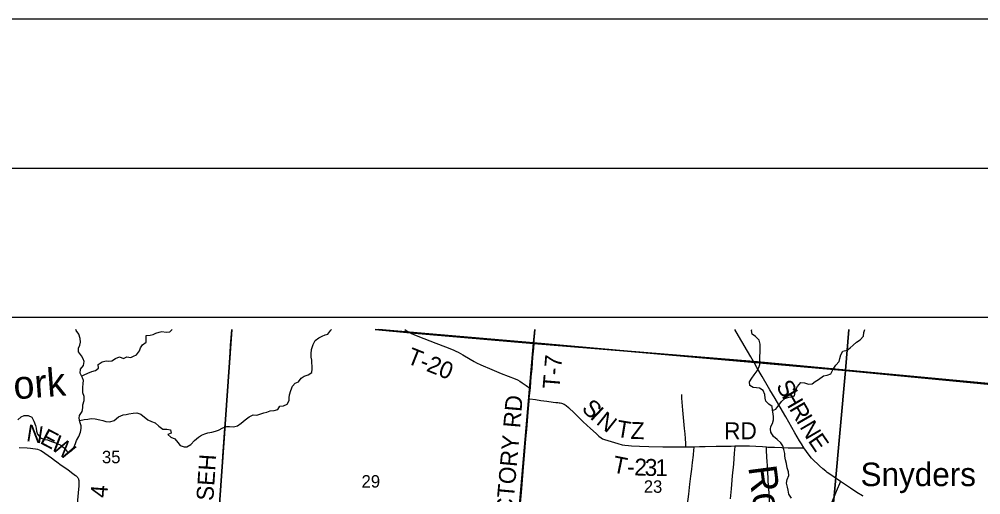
# Model space of a CAD drawing. Extents: x 0 to 34, y 0 to 22.
# Drawn here: x 3.306 to 6.536, y 20.403 to 22 of the extents above; entities that cross this region are included whole.
import ezdxf

# ---------------------------------------------------------------- set-up
doc = ezdxf.new("R2010")
doc.units = 0
for name, color, linetype in [('GM_X_Corporation', 7, 'Continuous'), ('GM_X_County_Road', 7, 'Continuous'), ('GM_X_County_Road_Text', 7, 'Continuous'), ('GM_X_Minor_River', 7, 'Continuous'), ('GM_X_Minor_River_Text', 7, 'Continuous'), ('GM_X_Section_Text', 7, 'Continuous'), ('GM_X_Township_Road', 7, 'Continuous'), ('GM_X_Township_Road_Text', 7, 'Continuous'), ('GM_X_Unincorporated_Text', 7, 'Continuous'), ('SH_Border', 7, 'Continuous'), ('SH_Cut_Line', 7, 'Continuous'), ('SH_Data', 7, 'Continuous')]:
    doc.layers.add(name, color=color, linetype=linetype)

msp = doc.modelspace()

# ---------------------------------------------------------------- linework, layer by layer
at = {"layer": 'GM_X_Corporation'}
for points in [[(4.0205, 20.9578), (3.9531, 20.0055), (2.9941, 20.0934), (3.0731, 20.9578)], [(4.5135, 20.9578), (5.0343, 20.9135), (4.9476, 19.9136), (3.9531, 20.0055), (4.0205, 20.9578)], [(4.9888, 20.3752), (4.9933, 20.4247), (4.9996, 20.4957), (5.004, 20.5483), (5.0073, 20.5914), (5.01, 20.6222), (5.015, 20.681), (5.018, 20.7181), (5.0187, 20.7263), (5.0223, 20.7637), (5.0238, 20.781), (5.0254, 20.7991), (5.0279, 20.8272), (5.031, 20.8652), (5.0337, 20.8956), (5.035, 20.9107), (4.6203, 20.9474), (4.5018, 20.9578)], [(4.5018, 20.9578), (4.6203, 20.9474), (5.035, 20.9107), (5.7735, 20.8502), (6.6577, 20.768)], [(5.0385, 20.9578), (5.0343, 20.9135), (4.5135, 20.9578)], [(6.0929, 20.9578), (6.0823, 20.8206), (5.0343, 20.9135), (5.0385, 20.9578)], [(7.1025, 20.9578), (7.0822, 20.7243), (6.0823, 20.8206), (6.0929, 20.9578)], [(6.6577, 20.768), (5.7735, 20.8502), (5.035, 20.9107), (5.0337, 20.8956), (5.031, 20.8652), (5.0279, 20.8272), (5.0254, 20.7991), (5.0238, 20.781), (5.0223, 20.7637), (5.0187, 20.7263), (5.018, 20.7181), (5.015, 20.681), (5.01, 20.6222), (5.0073, 20.5914), (5.004, 20.5483), (4.9996, 20.4957), (4.9933, 20.4247), (4.9888, 20.3752)]]:
    msp.add_lwpolyline(points, dxfattribs=at)
for points in [[(5.0343, 20.9135), (6.0823, 20.8206), (5.9917, 19.818), (4.9476, 19.9136)], [(6.0823, 20.8206), (7.0822, 20.7243), (6.9896, 19.7221), (5.9917, 19.818)]]:
    msp.add_lwpolyline(points, close=True, dxfattribs=at)
at = {"layer": 'GM_X_County_Road'}
for points in [[(5.7732, 20.8505), (5.7641, 20.8663), (5.7228, 20.9373), (5.7106, 20.9578)], [(5.9421, 20.561), (5.934, 20.574), (5.9278, 20.5847), (5.9122, 20.6116), (5.8812, 20.6652), (5.8703, 20.684), (5.8451, 20.7269), (5.8278, 20.7559), (5.8233, 20.7638), (5.8018, 20.8005), (5.7845, 20.8309), (5.7737, 20.8497), (5.7732, 20.8505)], [(3.3064, 20.5623), (3.3328, 20.5606), (3.3439, 20.5597), (3.3521, 20.5587), (3.3613, 20.5573), (3.3674, 20.5559), (3.3734, 20.5539), (3.3792, 20.5514), (3.3847, 20.5484), (3.3925, 20.5432), (3.4151, 20.5269), (3.4251, 20.5196), (3.4327, 20.5142), (3.4477, 20.5031), (3.4595, 20.4946), (3.4704, 20.4866), (3.4861, 20.4752), (3.4952, 20.4685), (3.4978, 20.4665), (3.5006, 20.4638), (3.5022, 20.4615), (3.5039, 20.4592), (3.5051, 20.4567), (3.5061, 20.454), (3.5067, 20.4509), (3.507, 20.4473), (3.5071, 20.4434), (3.5067, 20.4379), (3.5063, 20.4323), (3.5055, 20.4224), (3.4989, 20.3481)], [(6.0653, 20.4481), (6.0435, 20.4626), (6.026, 20.475), (6.0208, 20.4785), (6.0159, 20.4824), (6.0062, 20.4902), (5.9945, 20.5003), (5.9877, 20.5066), (5.9766, 20.5172), (5.9682, 20.5263), (5.9603, 20.5359), (5.951, 20.5482), (5.9421, 20.561)], [(6.1407, 20.3981), (6.1389, 20.3992), (6.1205, 20.4114), (6.0992, 20.4255), (6.0683, 20.4461), (6.0653, 20.4481)]]:
    msp.add_lwpolyline(points, dxfattribs=at)
at = {"layer": 'GM_X_Minor_River'}
for points in [[(3.3021, 20.6548), (3.3132, 20.665), (3.3231, 20.669), (3.3364, 20.6692), (3.3485, 20.6638), (3.356, 20.6504), (3.3615, 20.6359), (3.3629, 20.6264), (3.365, 20.6165), (3.3683, 20.6069), (3.3784, 20.5943), (3.3913, 20.5884), (3.4015, 20.5875), (3.4147, 20.582), (3.4246, 20.5785), (3.4344, 20.5753), (3.4465, 20.5699), (3.4589, 20.5595), (3.469, 20.5468), (3.4816, 20.5505), (3.4901, 20.5618), (3.4956, 20.5754), (3.4991, 20.5852), (3.5072, 20.5992), (3.5128, 20.6139), (3.5148, 20.6253), (3.5149, 20.6352), (3.5105, 20.6482), (3.508, 20.6604), (3.5089, 20.6699), (3.5174, 20.6831), (3.5202, 20.6956), (3.5204, 20.7054), (3.5247, 20.7198), (3.5245, 20.7331), (3.5197, 20.7461), (3.52, 20.7636), (3.5213, 20.7769), (3.5221, 20.7864), (3.5188, 20.7963), (3.5111, 20.8112), (3.5124, 20.8249), (3.5224, 20.8373), (3.5249, 20.8506), (3.5216, 20.8601), (3.516, 20.8697), (3.5059, 20.8827), (3.506, 20.8956), (3.5096, 20.9055), (3.5128, 20.9153), (3.5114, 20.9279), (3.5062, 20.942), (3.4981, 20.9546), (3.4963, 20.9578)], [(3.5095, 20.6531), (3.5247, 20.6556), (3.5372, 20.6574), (3.5486, 20.6591), (3.5616, 20.6586), (3.5767, 20.6546), (3.5873, 20.6522), (3.5979, 20.6494), (3.6108, 20.6481), (3.6249, 20.6521), (3.6399, 20.6653), (3.6552, 20.6712), (3.6654, 20.6729), (3.675, 20.6751), (3.6887, 20.6776), (3.7012, 20.6782), (3.7145, 20.6742), (3.7389, 20.655), (3.751, 20.6491), (3.7631, 20.6452), (3.7755, 20.6336), (3.7883, 20.6236), (3.8019, 20.6234), (3.8141, 20.621), (3.8173, 20.6096), (3.8051, 20.6055), (3.8157, 20.5967), (3.8289, 20.5908), (3.8394, 20.5789), (3.8472, 20.5689), (3.8601, 20.5638), (3.8699, 20.5637), (3.8833, 20.5715), (3.8957, 20.5858), (3.9087, 20.5967), (3.9191, 20.603), (3.9298, 20.6078), (3.9397, 20.6115), (3.953, 20.6136), (3.966, 20.6165), (3.9763, 20.6202), (3.9908, 20.6284), (4.0034, 20.6321), (4.0129, 20.6323), (4.0262, 20.6318), (4.0399, 20.635), (4.0518, 20.6433), (4.0652, 20.6545), (4.079, 20.6654), (4.092, 20.6717), (4.1045, 20.6708), (4.1179, 20.6748), (4.1286, 20.6789), (4.1385, 20.681), (4.1495, 20.6847), (4.1628, 20.6861), (4.175, 20.6893), (4.1813, 20.7007), (4.1938, 20.7024), (4.2068, 20.7072), (4.213, 20.7193), (4.2128, 20.7292), (4.214, 20.739), (4.2184, 20.7534), (4.2239, 20.7674), (4.2335, 20.778), (4.245, 20.7824), (4.2535, 20.7948), (4.2634, 20.8019), (4.2772, 20.8063), (4.2894, 20.8142), (4.2907, 20.8263), (4.2901, 20.8358), (4.2898, 20.8453), (4.2888, 20.8552), (4.287, 20.8648), (4.2868, 20.8765), (4.2881, 20.891), (4.2936, 20.908), (4.3007, 20.9208), (4.3133, 20.9302), (4.3244, 20.9358), (4.3339, 20.9398), (4.3435, 20.9424), (4.3535, 20.9563), (4.3555, 20.9578)], [(3.516, 20.8018), (3.5247, 20.8057), (3.5369, 20.812), (3.5499, 20.8168), (3.5628, 20.8201), (3.5724, 20.8283), (3.5711, 20.8405), (3.5852, 20.8498), (3.5982, 20.8527), (3.6077, 20.8522), (3.6176, 20.8529), (3.6302, 20.8611), (3.6432, 20.8663), (3.6568, 20.8604), (3.6675, 20.8664), (3.6808, 20.8643), (3.6903, 20.8687), (3.7003, 20.8736), (3.7099, 20.8871), (3.7142, 20.897), (3.7204, 20.9072), (3.7323, 20.9161), (3.7332, 20.9264), (3.7326, 20.9386), (3.7463, 20.9388), (3.7558, 20.9409), (3.7657, 20.9461), (3.7764, 20.9487), (3.7859, 20.9512), (3.8, 20.9488), (3.8129, 20.9501), (3.8205, 20.9578)], [(5.9004, 20.3923), (5.891, 20.4053), (5.8893, 20.4182), (5.8875, 20.4285), (5.8835, 20.4419), (5.886, 20.4548), (5.8911, 20.468), (5.8908, 20.4798), (5.8864, 20.4932), (5.8836, 20.508), (5.8807, 20.521), (5.8786, 20.5324), (5.8776, 20.542), (5.8751, 20.5549), (5.8714, 20.5675), (5.8647, 20.5771), (5.8523, 20.5894), (5.8403, 20.5994), (5.831, 20.6132), (5.8304, 20.6231), (5.8316, 20.6326), (5.8371, 20.6424), (5.8406, 20.6549), (5.8396, 20.6648), (5.839, 20.6747), (5.8365, 20.6869), (5.8359, 20.6991), (5.8246, 20.7072), (5.8145, 20.7176), (5.8123, 20.7275), (5.8113, 20.7404), (5.805, 20.7534), (5.793, 20.7616), (5.7835, 20.7624), (5.7717, 20.7633), (5.7604, 20.7699), (5.7598, 20.7821), (5.7676, 20.7953), (5.7749, 20.8063), (5.785, 20.8195), (5.7912, 20.8308), (5.7936, 20.841), (5.7947, 20.8684), (5.7953, 20.8805), (5.795, 20.89), (5.7955, 20.8999), (5.7956, 20.9094), (5.792, 20.9224), (5.7796, 20.9347), (5.7679, 20.9421), (5.7662, 20.9546), (5.7675, 20.9578)], [(5.9914, 20.7905), (6.0081, 20.8023), (6.0206, 20.8048), (6.0327, 20.8093), (6.0404, 20.8252), (6.0496, 20.8384), (6.061, 20.8505), (6.0634, 20.8607), (6.0661, 20.8736), (6.0734, 20.8857), (6.0871, 20.889), (6.0977, 20.8965), (6.1076, 20.9056), (6.1183, 20.9154), (6.1316, 20.9236), (6.1419, 20.9357), (6.1439, 20.9486), (6.1468, 20.9578)], [(5.8366, 20.6862), (5.8476, 20.6906), (5.8576, 20.7038), (5.8665, 20.7162), (5.878, 20.7267), (5.891, 20.7311), (5.9013, 20.7326), (5.9108, 20.7359), (5.9141, 20.7545), (5.9207, 20.7665), (5.9323, 20.7805), (5.944, 20.7796), (5.958, 20.7741), (5.9698, 20.7755), (5.9805, 20.7837), (5.9914, 20.7905)]]:
    msp.add_lwpolyline(points, dxfattribs=at)
at = {"layer": 'GM_X_Township_Road'}
for p, q in [((5.0352, 20.9101), (5.0395, 20.9578)), ((5.019, 20.7257), (5.0225, 20.7631))]:
    msp.add_line(p, q, dxfattribs=at)
for points in [[(3.9812, 20.3914), (3.9833, 20.4223), (3.9843, 20.4378), (3.9854, 20.4564), (3.9879, 20.4937), (3.9907, 20.534), (3.9941, 20.5805), (3.9986, 20.6425), (4.0002, 20.6642), (4.0027, 20.7014), (4.0058, 20.7448), (4.008, 20.7789), (4.0101, 20.8099), (4.0126, 20.8471), (4.0149, 20.8813), (4.0166, 20.9061), (4.0193, 20.9433), (4.0205, 20.9578)], [(4.6019, 20.9578), (4.6057, 20.9553), (4.6121, 20.9512), (4.6159, 20.9491), (4.6206, 20.9468)], [(4.6206, 20.9468), (4.6244, 20.945), (4.6315, 20.9419), (4.6455, 20.936), (4.7061, 20.9118), (4.7379, 20.8995), (4.764, 20.8895), (4.7725, 20.8858), (4.7808, 20.8817), (4.797, 20.8726), (4.8209, 20.8581), (4.8343, 20.8502), (4.8425, 20.8458), (4.8567, 20.8393), (4.894, 20.8238), (4.9256, 20.8107), (4.9487, 20.8017), (4.9718, 20.7925), (4.9802, 20.7887), (4.9884, 20.7844), (4.9962, 20.7794), (5.0088, 20.7704), (5.0141, 20.767), (5.0173, 20.7651), (5.0192, 20.7642), (5.0209, 20.7636), (5.0225, 20.7631)], [(5.0225, 20.7631), (5.0241, 20.7805), (5.0256, 20.7986), (5.0281, 20.8267), (5.0313, 20.8647), (5.0339, 20.895), (5.0352, 20.9101)], [(5.5459, 20.5641), (5.5458, 20.5666), (5.5454, 20.5749), (5.5445, 20.5917), (5.5429, 20.6074), (5.5409, 20.6253), (5.538, 20.6631), (5.5359, 20.6879), (5.5327, 20.7277), (5.5319, 20.7404)], [(4.9727, 20.1756), (4.9726, 20.1767), (4.9728, 20.186), (4.9738, 20.1984), (4.9776, 20.2417), (4.9852, 20.3314), (4.989, 20.3747), (4.9935, 20.4241), (4.9998, 20.4952), (5.0042, 20.5478), (5.0075, 20.5909), (5.0103, 20.6217), (5.0152, 20.6805), (5.0182, 20.7176), (5.019, 20.7257)], [(5.019, 20.7257), (5.0213, 20.7254), (5.0411, 20.7226), (5.0583, 20.7199), (5.0785, 20.7173), (5.1004, 20.7145), (5.1094, 20.7134), (5.116, 20.7126), (5.12, 20.7122), (5.1239, 20.7115), (5.1275, 20.7107), (5.1309, 20.7098), (5.1341, 20.7087), (5.1371, 20.7072), (5.1399, 20.7055), (5.1432, 20.7034), (5.1519, 20.6959), (5.1719, 20.6769), (5.2008, 20.6487), (5.2256, 20.6253), (5.2439, 20.6085), (5.2534, 20.6004), (5.2609, 20.5947), (5.2662, 20.5914), (5.272, 20.5888), (5.2839, 20.585), (5.3167, 20.5756), (5.3317, 20.5714), (5.3408, 20.5695), (5.3532, 20.5682), (5.3626, 20.5676), (5.3904, 20.5668), (5.4214, 20.5658), (5.468, 20.5644), (5.4866, 20.5641), (5.5146, 20.5637), (5.527, 20.5639), (5.5409, 20.564), (5.5459, 20.5641)], [(5.5434, 20.282), (5.5439, 20.2868), (5.5458, 20.309), (5.5484, 20.3373), (5.5514, 20.3714), (5.5551, 20.4051), (5.5593, 20.439), (5.5627, 20.4652), (5.5657, 20.4895), (5.5682, 20.5115), (5.571, 20.5363), (5.5728, 20.5544), (5.5733, 20.5612), (5.5735, 20.5646)], [(5.5459, 20.5641), (5.5671, 20.5645), (5.5735, 20.5646)], [(5.5735, 20.5646), (5.592, 20.5648), (5.6106, 20.5652), (5.6479, 20.566), (5.6976, 20.567), (5.7106, 20.5672)], [(5.7106, 20.5672), (5.7104, 20.5649), (5.7084, 20.5424), (5.7053, 20.5063), (5.7015, 20.4666), (5.6977, 20.4233), (5.6945, 20.39)], [(5.7106, 20.5672), (5.741, 20.5675), (5.7595, 20.5671), (5.7812, 20.5661), (5.8028, 20.5648), (5.8164, 20.5639), (5.8214, 20.5636), (5.8431, 20.5626), (5.8679, 20.5618), (5.8897, 20.5612), (5.9139, 20.561), (5.938, 20.5611), (5.9421, 20.561)], [(5.8281, 20.3615), (5.8251, 20.4085), (5.8226, 20.4498), (5.8205, 20.4873), (5.8179, 20.529), (5.8164, 20.5535), (5.8162, 20.5584), (5.8163, 20.5625), (5.8164, 20.5639)], [(6.0653, 20.4481), (6.0511, 20.4147), (6.0278, 20.3599)]]:
    msp.add_lwpolyline(points, dxfattribs=at)
at = {"layer": 'SH_Border'}
msp.add_lwpolyline([(1.5, 21.5), (33.5, 21.5), (33.5, 0.5), (1.5, 0.5)], close=True, dxfattribs=at)
at = {"layer": 'SH_Cut_Line'}
msp.add_lwpolyline([(0, 0), (34, 0), (34, 22), (0, 22)], close=True, dxfattribs=at)
at = {"layer": 'SH_Data'}
msp.add_line((2, 21), (9, 21), dxfattribs=at)

# ---------------------------------------------------------------- texts
at = {"layer": 'GM_X_County_Road_Text'}
for s, rotation, p in [('S', 300.135, (5.847, 20.7685)), ('H', 300.1335, (5.8663, 20.7353)), ('R', 300.1322, (5.8914, 20.6921)), ('I', 300.1439, (5.9148, 20.6517)), ('N', 351.0791, (3.328, 20.5839)), ('N', 300.2948, (5.9266, 20.6314)), ('E', 332.3463, (3.3728, 20.5777)), ('E', 304.3702, (5.9542, 20.5845)), ('W', 324.1832, (3.4086, 20.5591)), ('4', 85.5617, (3.6018, 20.3915))]:
    msp.add_text(s, height=0.0568, rotation=rotation, dxfattribs=at).set_placement(p)
at = {"layer": 'GM_X_Minor_River_Text'}
for s, height, rotation, p in [('Fork', 0.0947, 4.283, (3.213, 20.7178)), ('Rock', 0.0948, 277.3727, (5.7551, 20.4966))]:
    msp.add_text(s, height=height, rotation=rotation, dxfattribs=at).set_placement(p)
at = {"layer": 'GM_X_Section_Text'}
for s, p in [('35', (3.5843, 20.5091)), ('29', (4.4564, 20.4274)), ('23', (5.4043, 20.4099))]:
    msp.add_text(s, height=0.04186, rotation=0, dxfattribs=at).set_placement(p)
at = {"layer": 'GM_X_Township_Road_Text'}
for s, height, rotation, p in [('T-20', 0.05682, 338.2081, (4.6046, 20.8465)), ('T-7', 0.05682, 85.2348, (5.1209, 20.7568)), ('RD', 0.05682, 85.0738, (4.9887, 20.6259)), ('S', 0.0568, 315.9431, (5.1925, 20.6894)), ('I', 0.0568, 316.6682, (5.2209, 20.662)), ('N', 0.0568, 321.4964, (5.2416, 20.6427)), ('T', 0.0568, 350.666, (5.3095, 20.5988)), ('Z', 0.0568, 358.1557, (5.3594, 20.5912)), ('RD', 0.05682, 0, (5.6743, 20.5897)), ('VICTORY', 0.05682, 84.9299, (4.957, 20.2643)), ('TECUMSEH', 0.05682, 86.211, (3.9403, 20.112)), ('T', 0.0568, 348.5674, (5.2964, 20.4792)), ('2', 0.0568, 358.1401, (5.3717, 20.4684)), ('3', 0.0568, 358.2342, (5.4067, 20.4673)), ('1', 0.0568, 359.3626, (5.443, 20.4662)), ('-', 0.0568, 357.079, (5.3472, 20.4697))]:
    msp.add_text(s, height=height, rotation=rotation, dxfattribs=at).set_placement(p)
at = {"layer": 'GM_X_Unincorporated_Text'}
msp.add_text('Snyders', height=0.07898, rotation=0, dxfattribs=at).set_placement((6.1326, 20.4323))

doc.saveas('drawing.dxf')
